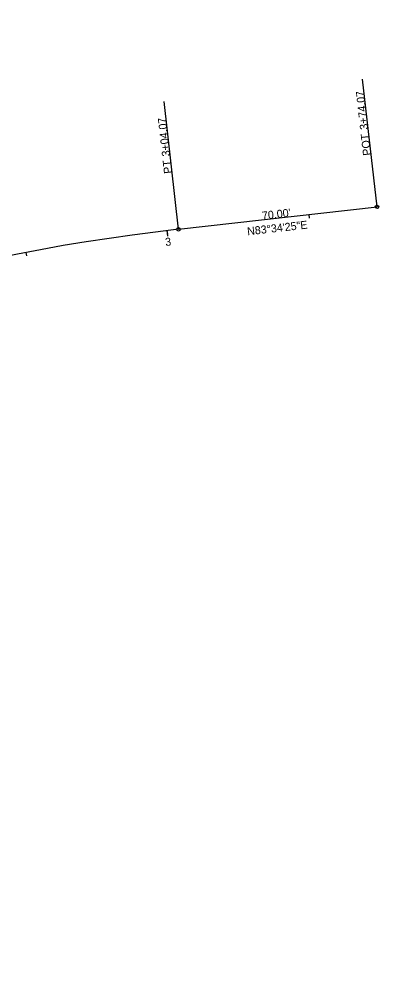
# Model space of a CAD drawing. Extents: x 1492452 to 1496782, y 514026 to 517659.
# Drawn here: x 1494779 to 1494904.9, y 514788.1 to 515125.3 of the extents above; entities that cross this region are included whole.
import ezdxf

# ---------------------------------------------------------------- set-up
doc = ezdxf.new("R2010")
doc.units = 0
for name, color, linetype in [('Default', 7, 'Continuous'), ('DR_X_Ditch', 7, 'Continuous'), ('DT_X_Break_Line', 7, 'Continuous'), ('DT_X_TIN_Hull', 7, 'Continuous'), ('DT_X_Void', 7, 'Continuous'), ('GE_X_Cells', 7, 'Continuous'), ('RD_X_Cells', 7, 'Continuous'), ('RD_X_GR_Lt', 7, 'Continuous'), ('SV_X_Random_Point', 7, 'Continuous'), ('UT_X_Electric_Cells', 7, 'Continuous'), ('UT_X_Misc_Cells', 7, 'Continuous'), ('UT_X_Water', 7, 'Continuous'), ('UT_X_Water_Cells', 7, 'Continuous')]:
    doc.layers.add(name, color=color, linetype=linetype)

msp = doc.modelspace()

# ---------------------------------------------------------------- linework, layer by layer
at = {"layer": 'Default'}
msp.add_line((1494834.78, 515051.74), (1494904.34, 515059.58), dxfattribs=at)
for centre, radius, start, end in [((1486425.91, 524780.42), 12277.67, 302.444021, 313.600151), ((1494914.94, 514340.04), 716.2, 96.42645, 117.27596)]:
    msp.add_arc(centre, radius, start, end, dxfattribs=at)
at = {"layer": 'DT_X_TIN_Hull'}
for p, q in [((1494880.42, 515056.88), (1494880.56, 515055.69)), ((1494830.74, 515051.28), (1494830.97, 515049.29)), ((1494781.33, 515043.67), (1494781.55, 515042.49))]:
    msp.add_line(p, q, dxfattribs=at)
at = {"layer": 'DT_X_Void'}
for p, q in [((1494904.34, 515059.58), (1494899.3, 515104.29)), ((1494834.78, 515051.74), (1494829.74, 515096.46))]:
    msp.add_line(p, q, dxfattribs=at)
for centre in [(1494904.34, 515059.58), (1494834.78, 515051.74)]:
    msp.add_circle(centre, 0.6, dxfattribs=at)
at = {"layer": 'GE_X_Cells'}
msp.add_line((1494834.78, 515051.74), (1494904.34, 515059.58), dxfattribs=at)
for centre, radius, start, end in [((1486425.91, 524780.42), 12277.67, 302.444021, 313.600151), ((1494914.94, 514340.04), 716.2, 96.42645, 117.27596)]:
    msp.add_arc(centre, radius, start, end, dxfattribs=at)
at = {"layer": 'RD_X_Cells'}
for p, q in [((1494904.34, 515059.58), (1494899.3, 515104.29)), ((1494834.78, 515051.74), (1494829.74, 515096.46))]:
    msp.add_line(p, q, dxfattribs=at)
for centre in [(1494904.34, 515059.58), (1494834.78, 515051.74)]:
    msp.add_circle(centre, 0.6, dxfattribs=at)
at = {"layer": 'UT_X_Misc_Cells'}
for p, q in [((1494904.34, 515059.58), (1494899.3, 515104.29)), ((1494834.78, 515051.74), (1494829.74, 515096.46))]:
    msp.add_line(p, q, dxfattribs=at)
for centre in [(1494904.34, 515059.58), (1494834.78, 515051.74)]:
    msp.add_circle(centre, 0.6, dxfattribs=at)
at = {"layer": 'UT_X_Water_Cells'}
msp.add_line((1494830.74, 515051.28), (1494830.88, 515050.08), dxfattribs=at)

# ---------------------------------------------------------------- texts
at = {"layer": 'DR_X_Ditch'}
msp.add_text("70.00'", height=2.8, rotation=6.4264, dxfattribs=at).set_placement((1494864.19, 515055.1))
at = {"layer": 'DT_X_Break_Line'}
msp.add_text('N83°34\'25"E', height=2.8, rotation=6.4264, dxfattribs=at).set_placement((1494858.99, 515049.64))
at = {"layer": 'DT_X_TIN_Hull'}
msp.add_text('3', height=2.8, rotation=6.752, dxfattribs=at).set_placement((1494830.28, 515045.88))
at = {"layer": 'DT_X_Void'}
for s, p in [('3+74.07', (1494901.23, 515086.77)), ('3+04.07', (1494831.84, 515077.42)), ('POT', (1494902.25, 515077.69)), ('PT', (1494832.52, 515071.37))]:
    msp.add_text(s, height=2.8, rotation=96.4264, dxfattribs=at).set_placement(p)
at = {"layer": 'RD_X_Cells'}
for s, p in [('3+74.07', (1494901.23, 515086.77)), ('3+04.07', (1494831.84, 515077.42)), ('POT', (1494902.25, 515077.69)), ('PT', (1494832.52, 515071.37))]:
    msp.add_text(s, height=2.8, rotation=96.4264, dxfattribs=at).set_placement(p)
at = {"layer": 'RD_X_GR_Lt'}
msp.add_text("70.00'", height=2.8, rotation=6.4264, dxfattribs=at).set_placement((1494864.19, 515055.1))
at = {"layer": 'SV_X_Random_Point'}
msp.add_text('N83°34\'25"E', height=2.8, rotation=6.4264, dxfattribs=at).set_placement((1494858.99, 515049.64))
at = {"layer": 'UT_X_Electric_Cells'}
msp.add_text('N83°34\'25"E', height=2.8, rotation=6.4264, dxfattribs=at).set_placement((1494858.99, 515049.64))
at = {"layer": 'UT_X_Misc_Cells'}
for s, p in [('3+74.07', (1494901.23, 515086.77)), ('3+04.07', (1494831.84, 515077.42)), ('POT', (1494902.25, 515077.69)), ('PT', (1494832.52, 515071.37))]:
    msp.add_text(s, height=2.8, rotation=96.4264, dxfattribs=at).set_placement(p)
at = {"layer": 'UT_X_Water'}
msp.add_text("70.00'", height=2.8, rotation=6.4264, dxfattribs=at).set_placement((1494864.19, 515055.1))

doc.saveas('drawing.dxf')
